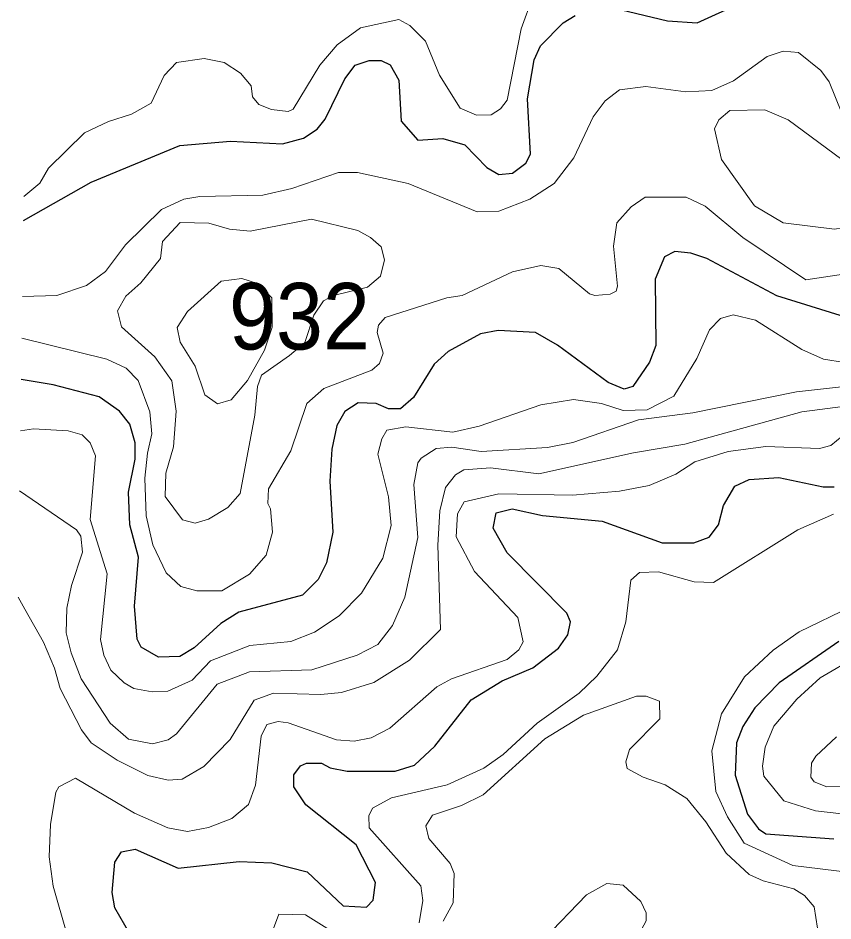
# Model space of a CAD drawing. Extents: x 763.2 to 816.8, y 7896.5 to 7952.7.
# Drawn here: x 763.296 to 765.256, y 7903.849 to 7906.02 of the extents above; entities that cross this region are included whole.
import ezdxf

# ---------------------------------------------------------------- set-up
doc = ezdxf.new("R2010")
doc.units = 0
doc.header["$LTSCALE"] = 0.064
doc.layers.add('1', color=7, linetype='Continuous', lineweight=25)
doc.layers.add('2', color=7, linetype='Continuous', lineweight=13)
doc.layers.add('21', color=7, linetype='Continuous')

msp = doc.modelspace()

# ---------------------------------------------------------------- linework, layer by layer
at = {"layer": '1'}
for points in [[(764.7273, 7906.045), (764.8578, 7906.0135), (764.9296, 7906.0088), (765.0337, 7906.0566)], [(763.3088, 7905.5337), (763.4718, 7905.6255), (763.6854, 7905.7143), (763.807, 7905.7244), (763.9319, 7905.718), (763.9824, 7905.7314), (764.0151, 7905.7532), (764.0343, 7905.7772), (764.0822, 7905.8746), (764.1071, 7905.9069), (764.1404, 7905.9184), (764.1692, 7905.9182), (764.1912, 7905.9076), (764.2117, 7905.8708), (764.2173, 7905.7724), (764.2575, 7905.7269), (764.3178, 7905.7309), (764.3705, 7905.7154), (764.4236, 7905.6611), (764.4525, 7905.6439), (764.4849, 7905.6478), (764.517, 7905.6715), (764.5289, 7905.6933), (764.5211, 7905.8262), (764.5374, 7905.9201), (764.5529, 7905.9537), (764.6071, 7906.0092), (764.636, 7906.0268)], [(765.2737, 7905.3055), (765.121, 7905.3525), (764.9531, 7905.4424), (764.9145, 7905.4551), (764.8754, 7905.4594), (764.851, 7905.446), (764.8288, 7905.3926), (764.8298, 7905.2332), (764.8147, 7905.193), (764.7746, 7905.1341), (764.7542, 7905.1282), (764.715, 7905.1444), (764.5932, 7905.2337), (764.5406, 7905.2641), (764.4504, 7905.2693), (764.4085, 7905.2607), (764.3304, 7905.2183), (764.297, 7905.1881), (764.2475, 7905.1078), (764.2158, 7905.081), (764.1867, 7905.0807), (764.157, 7905.0933), (764.1141, 7905.0948), (764.0816, 7905.0744), (764.0626, 7905.0408), (764.0506, 7904.9834), (764.0461, 7904.907), (764.0533, 7904.7841), (764.0376, 7904.7106), (764.0175, 7904.6706), (763.9802, 7904.633), (763.8268, 7904.5916), (763.7835, 7904.5645), (763.7195, 7904.5057), (763.6852, 7904.4854), (763.6341, 7904.4833), (763.592, 7904.5077), (763.5826, 7904.5265), (763.576, 7904.6061), (763.5857, 7904.7237), (763.5647, 7904.8018), (763.5612, 7904.8807), (763.5774, 7904.9596), (763.5776, 7904.9993), (763.5651, 7905.0442), (763.5398, 7905.0753), (763.4914, 7905.1093), (763.3802, 7905.1388), (763.3034, 7905.1516)], [(763.5651, 7903.8179), (763.5291, 7903.8807), (763.5219, 7903.9177), (763.5284, 7903.9907), (763.5446, 7904.0153), (763.5777, 7904.0217), (763.6813, 7903.976), (763.8274, 7903.9923), (763.9063, 7903.989), (763.9917, 7903.9674), (764.0776, 7903.8858), (764.134, 7903.8824), (764.1499, 7903.8991), (764.1557, 7903.9414), (764.1092, 7904.032), (763.9885, 7904.1288), (763.9591, 7904.1714), (763.9591, 7904.2009), (763.9755, 7904.2223), (763.99, 7904.229), (764.0262, 7904.2288), (764.047, 7904.2178), (764.0879, 7904.2094), (764.2028, 7904.2096), (764.2497, 7904.2242), (764.2985, 7904.2695), (764.3859, 7904.3813), (764.4606, 7904.4264), (764.5341, 7904.4575), (764.5963, 7904.5052), (764.618, 7904.5371), (764.6251, 7904.5683), (764.6156, 7904.5893), (764.4723, 7904.7347), (764.439, 7904.7937), (764.4458, 7904.8304), (764.4848, 7904.8402), (764.5571, 7904.824), (764.701, 7904.8109), (764.8456, 7904.7585), (764.9211, 7904.7582), (764.9585, 7904.7721), (764.9805, 7904.802), (764.9928, 7904.8486), (765.0202, 7904.895), (765.0542, 7904.9111), (765.1257, 7904.9159), (765.2325, 7904.8933), (765.2587, 7904.8931)], [(765.27, 7904.5215), (765.1264, 7904.4217), (765.0683, 7904.3621), (765.0391, 7904.3168), (765.0242, 7904.2773), (765.0205, 7904.1996), (765.0503, 7904.1058), (765.0769, 7904.0711), (765.0943, 7904.0586), (765.2579, 7904.0463)]]:
    msp.add_lwpolyline(points, dxfattribs=at)
at = {"layer": '2'}
for points in [[(764.5341, 7906.0722), (764.5065, 7905.9941), (764.4721, 7905.8229), (764.4567, 7905.8023), (764.4338, 7905.788), (764.3983, 7905.7865), (764.3594, 7905.804), (764.3093, 7905.8833), (764.2761, 7905.9648), (764.2381, 7906.0023), (764.2119, 7906.0169), (764.12, 7905.9972), (764.0635, 7905.9558), (764.022, 7905.907), (763.9576, 7905.801), (763.9459, 7905.7953), (763.9057, 7905.8003), (763.8748, 7905.8126), (763.8601, 7905.8312), (763.8564, 7905.8578), (763.8312, 7905.8882), (763.7914, 7905.9138), (763.7438, 7905.9232), (763.677, 7905.9135), (763.6472, 7905.8825), (763.616, 7905.816), (763.5685, 7905.789)], [(767.0083, 7906.0422), (766.9204, 7905.902), (766.8586, 7905.7384), (766.8345, 7905.6318), (766.8282, 7905.5751), (766.7926, 7905.4383), (766.7805, 7905.4141), (766.7415, 7905.3805), (766.6961, 7905.3663), (766.5992, 7905.3729), (766.4938, 7905.3695), (766.2965, 7905.3237), (766.2155, 7905.3316), (766.1326, 7905.3224), (766.0329, 7905.3203), (765.9395, 7905.327), (765.7561, 7905.3531), (765.6864, 7905.3496), (765.6422, 7905.3392), (765.5887, 7905.3033), (765.4576, 7905.1741), (765.3779, 7905.145), (765.1685, 7905.1214)], [(763.3062, 7905.3506), (763.3895, 7905.3531), (763.4606, 7905.377), (763.5059, 7905.4112), (763.5547, 7905.4752), (763.6406, 7905.5604), (763.6949, 7905.5852), (763.7328, 7905.5914), (763.8851, 7905.5944), (763.9541, 7905.6108), (764.0667, 7905.6487), (764.1127, 7905.6489), (764.2344, 7905.6228), (764.4002, 7905.5543), (764.452, 7905.5563), (764.5269, 7905.5846), (764.5852, 7905.6228), (764.6331, 7905.684), (764.6792, 7905.7826), (764.7084, 7905.8215), (764.7424, 7905.8482), (764.8057, 7905.8561), (764.9022, 7905.8429), (764.9647, 7905.8462), (765.0166, 7905.8692), (765.0977, 7905.9283), (765.1364, 7905.9411), (765.1732, 7905.9379), (765.2271, 7905.8943), (765.247, 7905.8673), (765.2771, 7905.792)], [(763.5685, 7905.789), (763.5137, 7905.7716), (763.4561, 7905.7442), (763.3694, 7905.6591), (763.3481, 7905.6232), (763.3096, 7905.5917)], [(765.2818, 7905.4045), (765.1907, 7905.3912), (765.0397, 7905.4928), (764.949, 7905.568), (764.9029, 7905.5897), (764.8046, 7905.5897), (764.7707, 7905.5667), (764.736, 7905.5277), (764.728, 7905.4715), (764.7378, 7905.3753), (764.7343, 7905.3633), (764.7206, 7905.3563), (764.6835, 7905.3532), (764.6701, 7905.3576), (764.5971, 7905.4182), (764.5538, 7905.4254), (764.4849, 7905.4105), (764.3641, 7905.3536), (764.3274, 7905.3476), (764.1792, 7905.3003), (764.1629, 7905.2819), (764.1597, 7905.264), (764.1741, 7905.2142), (764.1652, 7905.1901), (764.1469, 7905.1737), (764.0313, 7905.1296), (763.9904, 7905.0933), (763.9523, 7904.98), (763.8982, 7904.888), (763.8965, 7904.8533), (763.9029, 7904.8405), (763.9079, 7904.7843), (763.8929, 7904.7287), (763.8524, 7904.6832), (763.7861, 7904.6434), (763.7262, 7904.6432), (763.6874, 7904.6535), (763.6519, 7904.6861), (763.6205, 7904.7533), (763.604, 7904.8231), (763.6007, 7904.9143), (763.6076, 7904.9739), (763.6178, 7905.0209), (763.613, 7905.0732), (763.5851, 7905.1492), (763.5562, 7905.1786), (763.5092, 7905.2), (763.3048, 7905.2509)], [(763.3016, 7905.0279), (763.3329, 7905.0323), (763.4165, 7905.0276), (763.4504, 7905.0178), (763.4694, 7904.999), (763.4823, 7904.9674), (763.4695, 7904.8142), (763.5102, 7904.6837), (763.4939, 7904.5259), (763.5019, 7904.4883), (763.5191, 7904.4522), (763.5508, 7904.4219), (763.5744, 7904.4083), (763.6188, 7904.4001), (763.6559, 7904.4015), (763.715, 7904.4279), (763.7592, 7904.475), (763.8537, 7904.5116), (763.9523, 7904.5216), (764.0088, 7904.5433), (764.0683, 7904.5832), (764.1219, 7904.6371), (764.1731, 7904.7217), (764.1934, 7904.8004), (764.1872, 7904.869), (764.1613, 7904.9717), (764.1706, 7905.0086), (764.1831, 7905.0293), (764.2284, 7905.0375), (764.3415, 7905.0247), (764.4053, 7905.0392), (764.5538, 7905.0901), (764.6321, 7905.1032), (764.6996, 7905.0939), (764.7517, 7905.0771), (764.809, 7905.0785), (764.8735, 7905.1113), (764.9289, 7905.2015), (764.959, 7905.2704), (764.9856, 7905.2983), (765.0162, 7905.3068), (765.0698, 7905.2939), (765.1816, 7905.2235), (765.2336, 7905.2005), (765.2842, 7905.1921)], [(763.2959, 7904.6278), (763.3124, 7904.5987), (763.3571, 7904.5197), (763.3838, 7904.4567), (763.3969, 7904.4078), (763.4486, 7904.3092), (763.4714, 7904.2779), (763.5342, 7904.236), (763.6081, 7904.1987), (763.6572, 7904.188), (763.6909, 7904.1898), (763.743, 7904.2208), (763.8059, 7904.2855), (763.8639, 7904.3798), (763.9104, 7904.3966), (764.0246, 7904.3934), (764.0739, 7904.3983), (764.1521, 7904.4228), (764.2372, 7904.476), (764.3119, 7904.5498), (764.3057, 7904.7525), (764.3107, 7904.8351), (764.3242, 7904.8919), (764.3481, 7904.9218), (764.3679, 7904.9344), (764.4322, 7904.9389), (764.5487, 7904.9245), (764.7767, 7904.9749), (764.8997, 7904.9958), (765.1816, 7905.0737), (765.4346, 7905.1066)], [(765.1685, 7905.1214), (764.9191, 7905.0712), (764.7886, 7905.0543), (764.6301, 7905), (764.5695, 7904.9881), (764.4099, 7904.9785)], [(763.4129, 7903.818), (763.3801, 7903.933), (763.3706, 7904.0038), (763.3736, 7904.0812), (763.3871, 7904.1593), (763.3941, 7904.1715), (763.4344, 7904.1926), (763.5762, 7904.1081), (763.6565, 7904.0729), (763.7032, 7904.0647), (763.7544, 7904.0736), (763.8104, 7904.0956), (763.8506, 7904.1294), (763.8669, 7904.1756), (763.8804, 7904.2938), (763.8945, 7904.3217), (763.9214, 7904.3291), (763.9457, 7904.3259), (764.0616, 7904.2849), (764.1042, 7904.2817), (764.1455, 7904.2897), (764.1905, 7904.3129), (764.3035, 7904.4121), (764.3383, 7904.4316), (764.4727, 7904.4779), (764.5008, 7904.5014), (764.5108, 7904.5203), (764.4979, 7904.5788), (764.3939, 7904.6896), (764.3499, 7904.7726), (764.3533, 7904.8282), (764.3693, 7904.8574), (764.4526, 7904.8765), (764.6294, 7904.8733), (764.7429, 7904.8828), (764.8142, 7904.8965), (764.8785, 7904.9239), (764.9237, 7904.9535), (765.0042, 7904.9784), (765.0946, 7904.9898), (765.2236, 7904.985), (765.2507, 7904.9926), (765.2784, 7905.0149)], [(764.4099, 7904.9785), (764.3394, 7904.9882), (764.3015, 7904.985), (764.2652, 7904.9621), (764.2577, 7904.9505), (764.2482, 7904.8986), (764.2578, 7904.7713), (764.2264, 7904.6277), (764.197, 7904.5594), (764.1616, 7904.5139), (764.112, 7904.4881), (764.0023, 7904.4528), (763.8527, 7904.448), (763.7746, 7904.419), (763.6772, 7904.299), (763.6572, 7904.2848), (763.6197, 7904.2751), (763.5613, 7904.2867), (763.5176, 7904.3247), (763.448, 7904.4311), (763.4233, 7904.4937), (763.412, 7904.5418), (763.4133, 7904.6013), (763.4241, 7904.6556), (763.4508, 7904.7361), (763.447, 7904.7742), (763.4366, 7904.7901), (763.2996, 7904.8832)], [(765.2577, 7904.8271), (765.1718, 7904.7894), (764.9686, 7904.6632), (764.9226, 7904.6645), (764.8365, 7904.6891), (764.7911, 7904.6874), (764.7703, 7904.6689), (764.7575, 7904.5685), (764.738, 7904.5008), (764.6882, 7904.4378), (764.6458, 7904.3967), (764.5445, 7904.3247), (764.463, 7904.2498), (764.416, 7904.2167), (764.3285, 7904.1769), (764.1944, 7904.1455), (764.1486, 7904.1203), (764.1395, 7904.1018), (764.1403, 7904.073), (764.2647, 7903.9334), (764.2694, 7903.8986), (764.2609, 7903.8447)], [(765.2974, 7903.9657), (765.1593, 7903.9824), (765.0428, 7904.0365), (765.0021, 7904.0998), (764.9741, 7904.1606), (764.9647, 7904.2584), (764.9884, 7904.3471), (765.0436, 7904.436), (765.112, 7904.5002), (765.1751, 7904.5444), (765.3006, 7904.6055)], [(765.3157, 7904.4867), (765.2257, 7904.4336), (765.1695, 7904.3829), (765.1143, 7904.3176), (765.0929, 7904.2668), (765.0864, 7904.2216), (765.0902, 7904.1974), (765.1378, 7904.1382), (765.2139, 7904.1144), (765.4176, 7904.0911)], [(764.3184, 7903.8487), (764.3424, 7903.893), (764.345, 7903.9637), (764.3353, 7903.9873), (764.2841, 7904.0476), (764.2765, 7904.0782), (764.293, 7904.104), (764.3625, 7904.1269), (764.4147, 7904.1522), (764.5627, 7904.287), (764.6564, 7904.3442), (764.7832, 7904.3898), (764.8069, 7904.3899), (764.8386, 7904.3774), (764.8396, 7904.335), (764.7664, 7904.2618), (764.7579, 7904.2322), (764.7615, 7904.2156), (764.7997, 7904.1948), (764.8529, 7904.1764), (764.9049, 7904.1439), (764.9505, 7904.0874), (764.9995, 7904.0123), (765.0545, 7903.9611), (765.0886, 7903.9455), (765.1624, 7903.9264), (765.1877, 7903.9105), (765.2112, 7903.8831), (765.2192, 7903.8322)], [(765.2645, 7904.2917), (765.2146, 7904.2454), (765.2048, 7904.2283), (765.2031, 7904.1952), (765.2109, 7904.1841), (765.2415, 7904.1715), (765.4164, 7904.1749)], [(764.7472, 7903.7387), (764.8067, 7903.8496), (764.8069, 7903.8691), (764.794, 7903.8962), (764.7518, 7903.9355), (764.7118, 7903.9396), (764.6634, 7903.9117), (764.5599, 7903.8045)], [(764.0771, 7903.8077), (763.9871, 7903.8638), (763.9235, 7903.8657), (763.9081, 7903.8246)]]:
    msp.add_lwpolyline(points, dxfattribs=at)
for points in [[(764.9878, 7905.6802), (764.9714, 7905.7543), (764.9816, 7905.776), (765.0077, 7905.7982), (765.0919, 7905.7994), (765.1487, 7905.7754), (765.296, 7905.6664), (765.3725, 7905.6567), (765.4004, 7905.6343), (765.4116, 7905.5877), (765.4051, 7905.5723), (765.3769, 7905.546), (765.2999, 7905.5192), (765.2599, 7905.5127), (765.1365, 7905.5278), (765.0677, 7905.5692)], [(764.1693, 7905.4699), (764.144, 7905.493), (764.1133, 7905.5092), (764.0016, 7905.537), (763.8544, 7905.5077), (763.8046, 7905.5126), (763.7545, 7905.5274), (763.6857, 7905.5284), (763.6436, 7905.4829), (763.6383, 7905.4426), (763.5914, 7905.3833), (763.5554, 7905.3518), (763.535, 7905.3162), (763.5447, 7905.2781), (763.6247, 7905.2057), (763.6661, 7905.148), (763.6759, 7905.0753), (763.6702, 7904.9894), (763.6514, 7904.9261), (763.65, 7904.8695), (763.6911, 7904.8141), (763.7216, 7904.8059), (763.7538, 7904.8152), (763.8006, 7904.8432), (763.8304, 7904.8769), (763.8651, 7905.0656), (763.8719, 7905.1344), (763.8813, 7905.1617), (763.9488, 7905.2093), (763.9854, 7905.2405), (764.0075, 7905.3056), (764.0309, 7905.3406), (764.0543, 7905.3531), (764.1365, 7905.3729), (764.1678, 7905.3999), (764.1772, 7905.4391)], [(763.8721, 7905.3823), (763.9064, 7905.3473), (763.9072, 7905.2769), (763.8888, 7905.2214), (763.8481, 7905.1487), (763.8089, 7905.102), (763.7753, 7905.0924), (763.7452, 7905.1145), (763.7219, 7905.1836), (763.6856, 7905.2411), (763.6783, 7905.276), (763.7037, 7905.3148), (763.7846, 7905.3875), (763.8341, 7905.3939)]]:
    msp.add_lwpolyline(points, close=True, dxfattribs=at)

# ---------------------------------------------------------------- texts
at = {"layer": '21', "width": 0.95}
msp.add_text('932', height=0.16, dxfattribs=at).set_placement((763.8032, 7905.2234))

doc.saveas('drawing.dxf')
